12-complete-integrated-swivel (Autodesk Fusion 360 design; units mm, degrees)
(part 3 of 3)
extrude "Extrude2" cut sketch "E Rear Bearing Cap Bolt seed" profile of C1 along normal blind 3 (= "capThickness")
circular_pattern "C-Pattern1" TotalAngle 360
chamfer "Chamfer1" distance 0.3 (= "bedRelief")
work_plane "WorkPlane1" AlongDistance -29 (= "hubFace - adapterThickness") ExtraOffset 0
sketch "F Adapter Flange sketch" plane through (-20.5061, -20.5061, 0) normal (0.7071, 0.7071, 0) x axis (0, 0, 1)
  circle C1 centre (0, 0) radius 38
  dimension "d967" diameter C1 = 76 (= "mountOD")
extrude "Extrude1" new body sketch "F Adapter Flange sketch" along normal blind 6 (= "adapterThickness")
work_plane "WorkPlane2" AlongDistance -23 (= "hubFace") ExtraOffset 0
sketch "F Centering Pilot sketch" plane through (-16.2635, -16.2635, 0) normal (0.7071, 0.7071, 0) x axis (0, 0, 1)
  circle C1 centre (0, 0) radius 25
  circle C2 centre (0, 0) radius 17
  dimension "d972" diameter C1 = 50 (= "pilotDiameter")
  dimension "d973" diameter C2 = 34 (= "pilotInside")
extrude "Extrude2" add sketch "F Centering Pilot sketch" along normal blind 2 (= "pilotHeight")
work_plane "WorkPlane3" AlongDistance -29 (= "hubFace - adapterThickness") ExtraOffset 0
sketch "F Shaft Clearance sketch" plane through (-20.5061, -20.5061, 0) normal (0.7071, 0.7071, 0) x axis (0, 0, 1)
  circle C1 centre (0, 0) radius 4.25
  dimension "d978" diameter C1 = 8.5 (= "shaftClearance")
extrude "Extrude3" cut sketch "F Shaft Clearance sketch" along normal blind 6 (= "adapterThickness")
work_plane "WorkPlane4" AlongDistance -29 (= "hubFace - adapterThickness") ExtraOffset 0
sketch "F Mount Holes" plane through (-20.5061, -20.5061, 0) normal (0.7071, 0.7071, 0) x axis (0, 0, 1)
  circle C1 centre (22.6274, 22.6274) radius 2.15
  circle C2 centre (-22.6274, 22.6274) radius 2.15
  circle C3 centre (-22.6274, -22.6274) radius 2.15
  circle C4 centre (22.6274, -22.6274) radius 2.15
  point P1 (0, 0)
  point P2 (22.6274, 22.6274)
  point P3 (-22.6274, 22.6274)
  point P4 (-22.6274, -22.6274)
  point P5 (22.6274, -22.6274)
  dimension "d983" distance P1 P2 = 22.6274 (= "abs(mountCircle / ( 2 * sqrt(2) ))")
  dimension "d984" distance P1 P2 = 22.6274 (= "abs(mountCircle / ( 2 * sqrt(2) ))")
  dimension "d985" diameter C1 = 4.3 (= "m4Clearance")
  dimension "d986" distance P1 P3 = 22.6274 (= "abs(-mountCircle / ( 2 * sqrt(2) ))")
  dimension "d987" distance P1 P3 = 22.6274 (= "abs(mountCircle / ( 2 * sqrt(2) ))")
  dimension "d988" diameter C2 = 4.3 (= "m4Clearance")
  dimension "d989" distance P1 P4 = 22.6274 (= "abs(-mountCircle / ( 2 * sqrt(2) ))")
  dimension "d990" distance P1 P4 = 22.6274 (= "abs(-mountCircle / ( 2 * sqrt(2) ))")
  dimension "d991" diameter C3 = 4.3 (= "m4Clearance")
  dimension "d992" distance P1 P5 = 22.6274 (= "abs(mountCircle / ( 2 * sqrt(2) ))")
  dimension "d993" distance P1 P5 = 22.6274 (= "abs(-mountCircle / ( 2 * sqrt(2) ))")
  dimension "d994" diameter C4 = 4.3 (= "m4Clearance")
extrude "Extrude4" cut sketch "F Mount Holes" along normal blind 6 (= "adapterThickness")
sketch "F Compression Sleeve Holes" plane through (-20.5061, -20.5061, 0) normal (0.7071, 0.7071, 0) x axis (0, 0, 1)
  line L1 (11.3137, 0) -> (0, 0)
  line L2 (0, 11.3137) -> (0, 0)
  line L3 (-11.3137, 0) -> (0, 0)
  line L4 (0, -11.3137) -> (0, 0)
  circle C1 centre (11.3137, 0) radius 4.1
  circle C2 centre (0, 11.3137) radius 4.1
  circle C3 centre (-11.3137, 0) radius 4.1
  circle C4 centre (0, -11.3137) radius 4.1
  point P1 (0, 0)
  point P2 (11.3137, 0)
  point P3 (0, 11.3137)
  point P5 (0, -11.3137)
  horizontal L1
  vertical L2
  horizontal L3
  vertical L4
  dimension "d997" distance P1 P2 = 11.3137 (= "abs(hubHoleSpacing / sqrt(2))")
  dimension "d998" diameter C1 = 8.2 (= "sleeveOD + sleeveAllowance")
  dimension "d999" distance P1 P3 = 11.3137 (= "abs(hubHoleSpacing / sqrt(2))")
  dimension "d1000" diameter C2 = 8.2 (= "sleeveOD + sleeveAllowance")
  dimension "d59" = 150 (= "bodyWidth")
  dimension "d1002" diameter C3 = 8.2 (= "sleeveOD + sleeveAllowance")
  dimension "d1003" distance P1 P5 = 11.3137 (= "abs(-hubHoleSpacing / sqrt(2))")
  dimension "d1004" diameter C4 = 8.2 (= "sleeveOD + sleeveAllowance")
  dimension "d1001" distance = 11.3137 (= "abs(-hubHoleSpacing / sqrt(2))")
extrude "Extrude5" cut sketch "F Compression Sleeve Holes" profile of C1 C2 C3 C4 along normal blind 6 (= "adapterThickness")
chamfer "Chamfer1" distance 0.4 (= "entryChamfer")
chamfer "Chamfer2" distance 0.3 (= "bedRelief")
work_plane "WorkPlane1" AlongDistance 0.5 (= "qFront") ExtraOffset 0
sketch "Front 608 sketch" plane through (0.3536, 0.3536, 0) normal (0.7071, 0.7071, 0) x axis (0, 0, 1)
  circle C1 centre (0, 0) radius 11
  circle C2 centre (0, 0) radius 4
  dimension "d1011" diameter C1 = 22 (= "bearingOD")
  dimension "d1012" diameter C2 = 8 (= "bearingID")
extrude "Extrude1" new body sketch "Front 608 sketch" along normal blind 7 (= "bearingWidth")
work_plane "WorkPlane2" AlongDistance 25.6 (= "qRearBearing") ExtraOffset 0
sketch "Rear 608 sketch" plane through (18.1019, 18.1019, 0) normal (0.7071, 0.7071, 0) x axis (0, 0, 1)
  circle C1 centre (0, 0) radius 11
  circle C2 centre (0, 0) radius 4
  dimension "d1017" diameter C1 = 22 (= "bearingOD")
  dimension "d1018" diameter C2 = 8 (= "bearingID")
extrude "Extrude2" new body sketch "Rear 608 sketch" along normal blind 7 (= "bearingWidth")
work_plane "WorkPlane1" AlongDistance -24 ExtraOffset 0
sketch "Metal Shaft sketch" plane through (-16.9706, -16.9706, 0) normal (0.7071, 0.7071, 0) x axis (0, 0, 1)
  circle C1 centre (0, 0) radius 4
  dimension "d1023" diameter C1 = 8
extrude "Extrude1" new body sketch "Metal Shaft sketch" along normal blind 60
work_plane "WorkPlane1" AlongDistance -3.5 (= "qFront - 4 mm") ExtraOffset 0
sketch "Front Inner Ring Spacer sketch" plane through (-2.4749, -2.4749, 0) normal (0.7071, 0.7071, 0) x axis (0, 0, 1)
  circle C1 centre (0, 0) radius 5
  circle C2 centre (0, 0) radius 4
  dimension "d1028" diameter C1 = 10
  dimension "d1029" diameter C2 = 8
extrude "Extrude1" new body sketch "Front Inner Ring Spacer sketch" along normal blind 4
work_plane "WorkPlane2" AlongDistance 7.5 (= "qFront + bearingWidth") ExtraOffset 0
sketch "Rear Inner Ring Spacer sketch" plane through (5.3033, 5.3033, 0) normal (0.7071, 0.7071, 0) x axis (0, 0, 1)
  circle C1 centre (0, 0) radius 5
  circle C2 centre (0, 0) radius 4
  dimension "d1034" diameter C1 = 10
  dimension "d1035" diameter C2 = 8
extrude "Extrude2" new body sketch "Rear Inner Ring Spacer sketch" along normal blind 4
work_plane "WorkPlane1" AlongDistance -12.5 (= "qFront - 13 mm") ExtraOffset 0
sketch "Front Collar Maximum Envelope sketch" plane through (-8.8388, -8.8388, 0) normal (0.7071, 0.7071, 0) x axis (0, 0, 1)
  circle C1 centre (0, 0) radius 11.2
  circle C2 centre (0, 0) radius 4
  dimension "d1040" diameter C1 = 22.4
  dimension "d1041" diameter C2 = 8
extrude "Extrude1" new body sketch "Front Collar Maximum Envelope sketch" along normal blind 9
work_plane "WorkPlane2" AlongDistance 11.5 (= "qFront + bearingWidth + 4 mm") ExtraOffset 0
sketch "Rear Collar Maximum Envelope sketch" plane through (8.1317, 8.1317, 0) normal (0.7071, 0.7071, 0) x axis (0, 0, 1)
  circle C1 centre (0, 0) radius 11.2
  circle C2 centre (0, 0) radius 4
  dimension "d1046" diameter C1 = 22.4
  dimension "d1047" diameter C2 = 8
extrude "Extrude2" new body sketch "Rear Collar Maximum Envelope sketch" along normal blind 9
work_plane "WorkPlane1" AlongDistance 0 ExtraOffset 0
sketch "Spacer Pattern Axis" plane through (0, 0, 0) normal (0.7071, 0.7071, 0) x axis (0, 0, 1)
  circle C1 centre (0, 0) radius 0.5
  dimension "d1052" diameter C1 = 1
work_plane "WorkPlane2" AlongDistance 10.6 (= "qFrontBack") ExtraOffset 0
sketch "Support Spacer OD" plane through (7.4953, 7.4953, 0) normal (0.7071, 0.7071, 0) x axis (0, 0, 1)
  line L1 (17, 0) -> (0, 0)
  circle C1 centre (17, 0) radius 3
  circle C2 centre (17, 0) radius 1.6
  point P1 (0, 0)
  point P2 (17, 0)
  horizontal L1
  dimension "d1055" distance P1 P2 = 17 (= "supportCircle / 2")
  dimension "d1056" diameter C1 = 6 (= "supportSpacerOD")
  dimension "d1057" diameter C2 = 3.2
extrude "Extrude1" new body sketch "Support Spacer OD" profile of C1 C2 along normal blind 12 (= "supportSpacer")
circular_pattern "C-Pattern1" TotalAngle 360
work_plane "WorkPlane1" AlongDistance -29 (= "hubFace - adapterThickness") ExtraOffset 0
sketch "Sleeve 1 Outer" plane through (-20.5061, -20.5061, 0) normal (0.7071, 0.7071, 0) x axis (0, 0, 1)
  line L1 (11.3137, 0) -> (0, 0)
  circle C1 centre (11.3137, 0) radius 4
  circle C2 centre (11.3137, 0) radius 2.15
  point P1 (0, 0)
  point P2 (11.3137, 0)
  horizontal L1
  dimension "d1064" distance P1 P2 = 11.3137 (= "abs(hubHoleSpacing / sqrt(2))")
  dimension "d1065" diameter C1 = 8 (= "sleeveOD")
  dimension "d1066" diameter C2 = 4.3
extrude "Extrude1" new body sketch "Sleeve 1 Outer" profile of C1 C2 along normal blind 6 (= "adapterThickness")
work_plane "WorkPlane2" AlongDistance -29 (= "hubFace - adapterThickness") ExtraOffset 0
sketch "Sleeve 2 Outer" plane through (-20.5061, -20.5061, 0) normal (0.7071, 0.7071, 0) x axis (0, 0, 1)
  line L1 (0, 11.3137) -> (0, 0)
  circle C1 centre (0, 11.3137) radius 4
  circle C2 centre (0, 11.3137) radius 2.15
  point P1 (0, 0)
  point P2 (0, 11.3137)
  vertical L1
  dimension "d1071" distance P1 P2 = 11.3137 (= "abs(hubHoleSpacing / sqrt(2))")
  dimension "d1072" diameter C1 = 8 (= "sleeveOD")
  dimension "d1073" diameter C2 = 4.3
extrude "Extrude2" new body sketch "Sleeve 2 Outer" profile of C1 C2 along normal blind 6 (= "adapterThickness")
work_plane "WorkPlane3" AlongDistance -29 (= "hubFace - adapterThickness") ExtraOffset 0
sketch "Sleeve 3 Outer" plane through (-20.5061, -20.5061, 0) normal (0.7071, 0.7071, 0) x axis (0, 0, 1)
  line L1 (-11.3137, 0) -> (0, 0)
  circle C1 centre (-11.3137, 0) radius 4
  circle C2 centre (-11.3137, 0) radius 2.15
  point P1 (0, 0)
  point P2 (-11.3137, 0)
  horizontal L1
  dimension "d1078" distance P1 P2 = 11.3137 (= "abs(-hubHoleSpacing / sqrt(2))")
  dimension "d1079" diameter C1 = 8 (= "sleeveOD")
  dimension "d1080" diameter C2 = 4.3
extrude "Extrude3" new body sketch "Sleeve 3 Outer" profile of C1 C2 along normal blind 6 (= "adapterThickness")
work_plane "WorkPlane4" AlongDistance -29 (= "hubFace - adapterThickness") ExtraOffset 0
sketch "Sleeve 4 Outer" plane through (-20.5061, -20.5061, 0) normal (0.7071, 0.7071, 0) x axis (0, 0, 1)
  line L1 (0, -11.3137) -> (0, 0)
  circle C1 centre (0, -11.3137) radius 4
  circle C2 centre (0, -11.3137) radius 2.15
  point P1 (0, 0)
  point P2 (0, -11.3137)
  vertical L1
  dimension "d1085" distance P1 P2 = 11.3137 (= "abs(-hubHoleSpacing / sqrt(2))")
  dimension "d1086" diameter C1 = 8 (= "sleeveOD")
  dimension "d1087" diameter C2 = 4.3
extrude "Extrude4" new body sketch "Sleeve 4 Outer" profile of C1 C2 along normal blind 6 (= "adapterThickness")
work_plane "WorkPlane1" AlongDistance -23 (= "hubFace") ExtraOffset 0
sketch "Sonic Hub Body sketch" plane through (-16.2635, -16.2635, 0) normal (0.7071, 0.7071, 0) x axis (0, 0, 1)
  circle C1 centre (0, 0) radius 16
  circle C2 centre (0, 0) radius 4
  dimension "d1092" diameter C1 = 32
  dimension "d1093" diameter C2 = 8
extrude "Extrude1" new body sketch "Sonic Hub Body sketch" along normal blind 8
work_plane "WorkPlane2" AlongDistance -15 (= "hubFace + 8 mm") ExtraOffset 0
sketch "Sonic Hub Pilot sketch" plane through (-10.6066, -10.6066, 0) normal (0.7071, 0.7071, 0) x axis (0, 0, 1)
  circle C1 centre (0, 0) radius 7
  circle C2 centre (0, 0) radius 4
  dimension "d1098" diameter C1 = 14
  dimension "d1099" diameter C2 = 8
extrude "Extrude2" add sketch "Sonic Hub Pilot sketch" along normal blind 2
work_plane "WorkPlane3" AlongDistance -23 (= "hubFace") ExtraOffset 0
sketch "Hub M4 Thread Envelopes" plane through (-16.2635, -16.2635, 0) normal (0.7071, 0.7071, 0) x axis (0, 0, 1)
  line L1 (11.3137, 0) -> (0, 0)
  line L2 (0, 11.3137) -> (0, 0)
  line L3 (-11.3137, 0) -> (0, 0)
  line L4 (0, -11.3137) -> (0, 0)
  circle C1 centre (11.3137, 0) radius 2.15
  circle C2 centre (0, 11.3137) radius 2.15
  circle C3 centre (-11.3137, 0) radius 2.15
  circle C4 centre (0, -11.3137) radius 2.15
  point P1 (0, 0)
  point P2 (11.3137, 0)
  point P3 (0, 11.3137)
  point P5 (0, -11.3137)
  horizontal L1
  vertical L2
  horizontal L3
  vertical L4
  dimension "d1104" distance P1 P2 = 11.3137 (= "abs(hubHoleSpacing / sqrt(2))")
  dimension "d1105" diameter C1 = 4.3
  dimension "d1106" distance P1 P3 = 11.3137 (= "abs(hubHoleSpacing / sqrt(2))")
  dimension "d1107" diameter C2 = 4.3
  dimension "d59" = 150 (= "bodyWidth")
  dimension "d1109" diameter C3 = 4.3
  dimension "d1110" distance P1 P5 = 11.3137 (= "abs(-hubHoleSpacing / sqrt(2))")
  dimension "d1111" diameter C4 = 4.3
  dimension "d1108" distance = 11.3137 (= "abs(-hubHoleSpacing / sqrt(2))")
extrude "Extrude3" cut sketch "Hub M4 Thread Envelopes" profile of C1 C2 C3 C4 along normal blind 8
work_plane "WorkPlane1" AlongDistance -30 (= "hubFace - adapterThickness - 1 mm") ExtraOffset 0
sketch "Hub Screw 1 Profile" plane through (-21.2132, -21.2132, 0) normal (0.7071, 0.7071, 0) x axis (0, 0, 1)
  line L1 (11.3137, 0) -> (0, 0)
  circle C1 centre (11.3137, 0) radius 2
  point P1 (0, 0)
  point P2 (11.3137, 0)
  horizontal L1
  dimension "d1116" distance P1 P2 = 11.3137 (= "abs(hubHoleSpacing / sqrt(2))")
  dimension "d1117" diameter C1 = 4
extrude "Extrude1" new body sketch "Hub Screw 1 Profile" profile of C1 along normal blind 12
work_plane "WorkPlane2" AlongDistance -34 (= "hubFace - adapterThickness - 5 mm") ExtraOffset 0
sketch "Hub Screw Head 1 Profile" plane through (-24.0416, -24.0416, 0) normal (0.7071, 0.7071, 0) x axis (0, 0, 1)
  line L1 (11.3137, 0) -> (0, 0)
  circle C1 centre (11.3137, 0) radius 3.5
  point P1 (0, 0)
  point P2 (11.3137, 0)
  horizontal L1
  dimension "d1122" distance P1 P2 = 11.3137 (= "abs(hubHoleSpacing / sqrt(2))")
  dimension "d1123" diameter C1 = 7
extrude "Extrude2" new body sketch "Hub Screw Head 1 Profile" profile of C1 along normal blind 4
work_plane "WorkPlane3" AlongDistance -30 (= "hubFace - adapterThickness - 1 mm") ExtraOffset 0
sketch "Hub Washer 1 Outer" plane through (-21.2132, -21.2132, 0) normal (0.7071, 0.7071, 0) x axis (0, 0, 1)
  line L1 (11.3137, 0) -> (0, 0)
  circle C1 centre (11.3137, 0) radius 6
  circle C2 centre (11.3137, 0) radius 2.15
  point P1 (0, 0)
  point P2 (11.3137, 0)
  horizontal L1
  dimension "d1128" distance P1 P2 = 11.3137 (= "abs(hubHoleSpacing / sqrt(2))")
  dimension "d1129" diameter C1 = 12
  dimension "d1130" diameter C2 = 4.3
extrude "Extrude3" new body sketch "Hub Washer 1 Outer" profile of C1 C2 along normal blind 1
work_plane "WorkPlane4" AlongDistance -30 (= "hubFace - adapterThickness - 1 mm") ExtraOffset 0
sketch "Hub Screw 2 Profile" plane through (-21.2132, -21.2132, 0) normal (0.7071, 0.7071, 0) x axis (0, 0, 1)
  line L1 (0, 11.3137) -> (0, 0)
  circle C1 centre (0, 11.3137) radius 2
  point P1 (0, 0)
  point P2 (0, 11.3137)
  vertical L1
  dimension "d1135" distance P1 P2 = 11.3137 (= "abs(hubHoleSpacing / sqrt(2))")
  dimension "d1136" diameter C1 = 4
extrude "Extrude4" new body sketch "Hub Screw 2 Profile" profile of C1 along normal blind 12
work_plane "WorkPlane5" AlongDistance -34 (= "hubFace - adapterThickness - 5 mm") ExtraOffset 0
sketch "Hub Screw Head 2 Profile" plane through (-24.0416, -24.0416, 0) normal (0.7071, 0.7071, 0) x axis (0, 0, 1)
  line L1 (0, 11.3137) -> (0, 0)
  circle C1 centre (0, 11.3137) radius 3.5
  point P1 (0, 0)
  point P2 (0, 11.3137)
  vertical L1
  dimension "d1141" distance P1 P2 = 11.3137 (= "abs(hubHoleSpacing / sqrt(2))")
  dimension "d1142" diameter C1 = 7
extrude "Extrude5" new body sketch "Hub Screw Head 2 Profile" profile of C1 along normal blind 4
work_plane "WorkPlane6" AlongDistance -30 (= "hubFace - adapterThickness - 1 mm") ExtraOffset 0
sketch "Hub Washer 2 Outer" plane through (-21.2132, -21.2132, 0) normal (0.7071, 0.7071, 0) x axis (0, 0, 1)
  line L1 (0, 11.3137) -> (0, 0)
  circle C1 centre (0, 11.3137) radius 6
  circle C2 centre (0, 11.3137) radius 2.15
  point P1 (0, 0)
  point P2 (0, 11.3137)
  vertical L1
  dimension "d1147" distance P1 P2 = 11.3137 (= "abs(hubHoleSpacing / sqrt(2))")
  dimension "d1148" diameter C1 = 12
  dimension "d1149" diameter C2 = 4.3
extrude "Extrude6" new body sketch "Hub Washer 2 Outer" profile of C1 C2 along normal blind 1
work_plane "WorkPlane7" AlongDistance -30 (= "hubFace - adapterThickness - 1 mm") ExtraOffset 0
sketch "Hub Screw 3 Profile" plane through (-21.2132, -21.2132, 0) normal (0.7071, 0.7071, 0) x axis (0, 0, 1)
  line L1 (-11.3137, 0) -> (0, 0)
  circle C1 centre (-11.3137, 0) radius 2
  point P1 (0, 0)
  point P2 (-11.3137, 0)
  horizontal L1
  dimension "d1154" distance P1 P2 = 11.3137 (= "abs(-hubHoleSpacing / sqrt(2))")
  dimension "d1155" diameter C1 = 4
extrude "Extrude7" new body sketch "Hub Screw 3 Profile" profile of C1 along normal blind 12
work_plane "WorkPlane8" AlongDistance -34 (= "hubFace - adapterThickness - 5 mm") ExtraOffset 0
sketch "Hub Screw Head 3 Profile" plane through (-24.0416, -24.0416, 0) normal (0.7071, 0.7071, 0) x axis (0, 0, 1)
  line L1 (-11.3137, 0) -> (0, 0)
  circle C1 centre (-11.3137, 0) radius 3.5
  point P1 (0, 0)
  point P2 (-11.3137, 0)
  horizontal L1
  dimension "d1160" distance P1 P2 = 11.3137 (= "abs(-hubHoleSpacing / sqrt(2))")
  dimension "d1161" diameter C1 = 7
extrude "Extrude8" new body sketch "Hub Screw Head 3 Profile" profile of C1 along normal blind 4
work_plane "WorkPlane9" AlongDistance -30 (= "hubFace - adapterThickness - 1 mm") ExtraOffset 0
sketch "Hub Washer 3 Outer" plane through (-21.2132, -21.2132, 0) normal (0.7071, 0.7071, 0) x axis (0, 0, 1)
  line L1 (-11.3137, 0) -> (0, 0)
  circle C1 centre (-11.3137, 0) radius 6
  circle C2 centre (-11.3137, 0) radius 2.15
  point P1 (0, 0)
  point P2 (-11.3137, 0)
  horizontal L1
  dimension "d1166" distance P1 P2 = 11.3137 (= "abs(-hubHoleSpacing / sqrt(2))")
  dimension "d1167" diameter C1 = 12
  dimension "d1168" diameter C2 = 4.3
extrude "Extrude9" new body sketch "Hub Washer 3 Outer" profile of C1 C2 along normal blind 1
work_plane "WorkPlane10" AlongDistance -30 (= "hubFace - adapterThickness - 1 mm") ExtraOffset 0
sketch "Hub Screw 4 Profile" plane through (-21.2132, -21.2132, 0) normal (0.7071, 0.7071, 0) x axis (0, 0, 1)
  line L1 (0, -11.3137) -> (0, 0)
  circle C1 centre (0, -11.3137) radius 2
  point P1 (0, 0)
  point P2 (0, -11.3137)
  vertical L1
  dimension "d1173" distance P1 P2 = 11.3137 (= "abs(-hubHoleSpacing / sqrt(2))")
  dimension "d1174" diameter C1 = 4
extrude "Extrude10" new body sketch "Hub Screw 4 Profile" profile of C1 along normal blind 12
work_plane "WorkPlane11" AlongDistance -34 (= "hubFace - adapterThickness - 5 mm") ExtraOffset 0
sketch "Hub Screw Head 4 Profile" plane through (-24.0416, -24.0416, 0) normal (0.7071, 0.7071, 0) x axis (0, 0, 1)
  line L1 (0, -11.3137) -> (0, 0)
  circle C1 centre (0, -11.3137) radius 3.5
  point P1 (0, 0)
  point P2 (0, -11.3137)
  vertical L1
  dimension "d1179" distance P1 P2 = 11.3137 (= "abs(-hubHoleSpacing / sqrt(2))")
  dimension "d1180" diameter C1 = 7
extrude "Extrude11" new body sketch "Hub Screw Head 4 Profile" profile of C1 along normal blind 4
work_plane "WorkPlane12" AlongDistance -30 (= "hubFace - adapterThickness - 1 mm") ExtraOffset 0
sketch "Hub Washer 4 Outer" plane through (-21.2132, -21.2132, 0) normal (0.7071, 0.7071, 0) x axis (0, 0, 1)
  line L1 (0, -11.3137) -> (0, 0)
  circle C1 centre (0, -11.3137) radius 6
  circle C2 centre (0, -11.3137) radius 2.15
  point P1 (0, 0)
  point P2 (0, -11.3137)
  vertical L1
  dimension "d1185" distance P1 P2 = 11.3137 (= "abs(-hubHoleSpacing / sqrt(2))")
  dimension "d1186" diameter C1 = 12
  dimension "d1187" diameter C2 = 4.3
extrude "Extrude12" new body sketch "Hub Washer 4 Outer" profile of C1 C2 along normal blind 1
work_plane "WorkPlane1" AlongDistance -30 (= "hubFace - adapterThickness - 1 mm") ExtraOffset 0
sketch "Adapter Screw 1 Profile" plane through (-21.2132, -21.2132, 0) normal (0.7071, 0.7071, 0) x axis (0, 0, 1)
  circle C1 centre (22.6274, 22.6274) radius 2
  point P1 (0, 0)
  point P2 (22.6274, 22.6274)
  dimension "d1192" distance P1 P2 = 22.6274 (= "abs(mountCircle / ( 2 * sqrt(2) ))")
  dimension "d1193" distance P1 P2 = 22.6274 (= "abs(mountCircle / ( 2 * sqrt(2) ))")
  dimension "d1194" diameter C1 = 4
extrude "Extrude1" new body sketch "Adapter Screw 1 Profile" along normal blind 30
work_plane "WorkPlane2" AlongDistance -34 (= "hubFace - adapterThickness - 5 mm") ExtraOffset 0
sketch "Adapter Screw Head 1 Profile" plane through (-24.0416, -24.0416, 0) normal (0.7071, 0.7071, 0) x axis (0, 0, 1)
  circle C1 centre (22.6274, 22.6274) radius 3.5
  point P1 (0, 0)
  point P2 (22.6274, 22.6274)
  dimension "d1199" distance P1 P2 = 22.6274 (= "abs(mountCircle / ( 2 * sqrt(2) ))")
  dimension "d1200" distance P1 P2 = 22.6274 (= "abs(mountCircle / ( 2 * sqrt(2) ))")
  dimension "d1201" diameter C1 = 7
extrude "Extrude2" new body sketch "Adapter Screw Head 1 Profile" along normal blind 4
work_plane "WorkPlane3" AlongDistance -30 (= "hubFace - adapterThickness - 1 mm") ExtraOffset 0
sketch "Adapter Washer 1 Outer" plane through (-21.2132, -21.2132, 0) normal (0.7071, 0.7071, 0) x axis (0, 0, 1)
  circle C1 centre (22.6274, 22.6274) radius 4.5
  circle C2 centre (22.6274, 22.6274) radius 2.15
  point P1 (0, 0)
  point P2 (22.6274, 22.6274)
  dimension "d1206" distance P1 P2 = 22.6274 (= "abs(mountCircle / ( 2 * sqrt(2) ))")
  dimension "d1207" distance P1 P2 = 22.6274 (= "abs(mountCircle / ( 2 * sqrt(2) ))")
  dimension "d1208" diameter C1 = 9
  dimension "d1209" diameter C2 = 4.3
extrude "Extrude3" new body sketch "Adapter Washer 1 Outer" along normal blind 1
work_plane "WorkPlane4" ExtraOffset 0
sketch "Adapter Nut Hex 1" plane through (-3.182, -3.182, 0) normal (0.7071, 0.7071, 0) x axis (0, 0, 1)
  line L1 (24.6481, 26.1274) -> (26.6689, 22.6274)
  line L2 (20.6067, 26.1274) -> (24.6481, 26.1274)
  line L3 (18.586, 22.6274) -> (20.6067, 26.1274)
  line L4 (20.6067, 19.1274) -> (18.586, 22.6274)
  line L5 (24.6481, 19.1274) -> (20.6067, 19.1274)
  line L6 (26.6689, 22.6274) -> (24.6481, 19.1274)
  circle C1 centre (22.6274, 22.6274) radius 4.0415
  point P3 (26.6689, 22.6274)
  point P4 (24.6481, 26.1274)
  point P5 (20.6067, 26.1274)
  point P6 (18.586, 22.6274)
  point P7 (20.6067, 19.1274)
  point P8 (24.6481, 19.1274)
  point P1 (0, 0)
  point P2 (22.6274, 22.6274)
  coincident C1 P3
  coincident C1 P4
  coincident C1 P5
  coincident C1 P6
  coincident C1 P7
  coincident C1 P8
  equal L1 L2
  equal L1 L3
  equal L1 L4
  equal L1 L5
  equal L1 L6
  horizontal L2
  dimension "d1214" distance P1 P2 = 22.6274 (= "abs(mountCircle / ( 2 * sqrt(2) ))")
  dimension "d1215" distance P1 P2 = 22.6274 (= "abs(mountCircle / ( 2 * sqrt(2) ))")
  dimension "d1216" diameter C1 = 8.0829 (= "2 * ( 7 mm ) / sqrt(3)")
extrude "Extrude4" new body sketch "Adapter Nut Hex 1" profile of L1 L2 L3 L4 L5 L6 along normal blind 3.2
sketch "Nut Thread Clearance 1" plane through (-3.182, -3.182, 0) normal (0.7071, 0.7071, 0) x axis (0, 0, 1)
  circle C1 centre (22.6274, 22.6274) radius 2.15
  point P1 (0, 0)
  point P2 (22.6274, 22.6274)
  dimension "d1219" distance P1 P2 = 22.6274 (= "abs(mountCircle / ( 2 * sqrt(2) ))")
  dimension "d1220" distance P1 P2 = 22.6274 (= "abs(mountCircle / ( 2 * sqrt(2) ))")
  dimension "d1221" diameter C1 = 4.3
extrude "Extrude5" cut sketch "Nut Thread Clearance 1" along normal blind 3.2
work_plane "WorkPlane5" AlongDistance -30 (= "hubFace - adapterThickness - 1 mm") ExtraOffset 0
sketch "Adapter Screw 2 Profile" plane through (-21.2132, -21.2132, 0) normal (0.7071, 0.7071, 0) x axis (0, 0, 1)
  circle C1 centre (-22.6274, 22.6274) radius 2
  point P1 (0, 0)
  point P2 (-22.6274, 22.6274)
  dimension "d1226" distance P1 P2 = 22.6274 (= "abs(-mountCircle / ( 2 * sqrt(2) ))")
  dimension "d1227" distance P1 P2 = 22.6274 (= "abs(mountCircle / ( 2 * sqrt(2) ))")
  dimension "d1228" diameter C1 = 4
extrude "Extrude6" new body sketch "Adapter Screw 2 Profile" along normal blind 30
work_plane "WorkPlane6" AlongDistance -34 (= "hubFace - adapterThickness - 5 mm") ExtraOffset 0
sketch "Adapter Screw Head 2 Profile" plane through (-24.0416, -24.0416, 0) normal (0.7071, 0.7071, 0) x axis (0, 0, 1)
  circle C1 centre (-22.6274, 22.6274) radius 3.5
  point P1 (0, 0)
  point P2 (-22.6274, 22.6274)
  dimension "d1233" distance P1 P2 = 22.6274 (= "abs(-mountCircle / ( 2 * sqrt(2) ))")
  dimension "d1234" distance P1 P2 = 22.6274 (= "abs(mountCircle / ( 2 * sqrt(2) ))")
  dimension "d1235" diameter C1 = 7
extrude "Extrude7" new body sketch "Adapter Screw Head 2 Profile" along normal blind 4
work_plane "WorkPlane7" AlongDistance -30 (= "hubFace - adapterThickness - 1 mm") ExtraOffset 0
sketch "Adapter Washer 2 Outer" plane through (-21.2132, -21.2132, 0) normal (0.7071, 0.7071, 0) x axis (0, 0, 1)
  circle C1 centre (-22.6274, 22.6274) radius 4.5
  circle C2 centre (-22.6274, 22.6274) radius 2.15
  point P1 (0, 0)
  point P2 (-22.6274, 22.6274)
  dimension "d1240" distance P1 P2 = 22.6274 (= "abs(-mountCircle / ( 2 * sqrt(2) ))")
  dimension "d1241" distance P1 P2 = 22.6274 (= "abs(mountCircle / ( 2 * sqrt(2) ))")
  dimension "d1242" diameter C1 = 9
  dimension "d1243" diameter C2 = 4.3
extrude "Extrude8" new body sketch "Adapter Washer 2 Outer" along normal blind 1
work_plane "WorkPlane8" ExtraOffset 0
sketch "Adapter Nut Hex 2" plane through (-3.182, -3.182, 0) normal (0.7071, 0.7071, 0) x axis (0, 0, 1)
  line L1 (-20.6067, 26.1274) -> (-18.586, 22.6274)
  line L2 (-24.6481, 26.1274) -> (-20.6067, 26.1274)
  line L3 (-26.6689, 22.6274) -> (-24.6481, 26.1274)
  line L4 (-24.6481, 19.1274) -> (-26.6689, 22.6274)
  line L5 (-20.6067, 19.1274) -> (-24.6481, 19.1274)
  line L6 (-18.586, 22.6274) -> (-20.6067, 19.1274)
  circle C1 centre (-22.6274, 22.6274) radius 4.0415
  point P3 (-18.586, 22.6274)
  point P4 (-20.6067, 26.1274)
  point P5 (-24.6481, 26.1274)
  point P6 (-26.6689, 22.6274)
  point P7 (-24.6481, 19.1274)
  point P8 (-20.6067, 19.1274)
  point P1 (0, 0)
  point P2 (-22.6274, 22.6274)
  coincident C1 P3
  coincident C1 P4
  coincident C1 P5
  coincident C1 P6
  coincident C1 P7
  coincident C1 P8
  equal L1 L2
  equal L1 L3
  equal L1 L4
  equal L1 L5
  equal L1 L6
  horizontal L2
  dimension "d1248" distance P1 P2 = 22.6274 (= "abs(-mountCircle / ( 2 * sqrt(2) ))")
  dimension "d1249" distance P1 P2 = 22.6274 (= "abs(mountCircle / ( 2 * sqrt(2) ))")
  dimension "d1250" diameter C1 = 8.0829 (= "2 * ( 7 mm ) / sqrt(3)")
extrude "Extrude9" new body sketch "Adapter Nut Hex 2" profile of L1 L2 L3 L4 L5 L6 along normal blind 3.2
sketch "Nut Thread Clearance 2" plane through (-3.182, -3.182, 0) normal (0.7071, 0.7071, 0) x axis (0, 0, 1)
  circle C1 centre (-22.6274, 22.6274) radius 2.15
  point P1 (0, 0)
  point P2 (-22.6274, 22.6274)
  dimension "d1253" distance P1 P2 = 22.6274 (= "abs(-mountCircle / ( 2 * sqrt(2) ))")
  dimension "d1254" distance P1 P2 = 22.6274 (= "abs(mountCircle / ( 2 * sqrt(2) ))")
  dimension "d1255" diameter C1 = 4.3
extrude "Extrude10" cut sketch "Nut Thread Clearance 2" along normal blind 3.2
work_plane "WorkPlane9" AlongDistance -30 (= "hubFace - adapterThickness - 1 mm") ExtraOffset 0
sketch "Adapter Screw 3 Profile" plane through (-21.2132, -21.2132, 0) normal (0.7071, 0.7071, 0) x axis (0, 0, 1)
  circle C1 centre (-22.6274, -22.6274) radius 2
  point P1 (0, 0)
  point P2 (-22.6274, -22.6274)
  dimension "d1260" distance P1 P2 = 22.6274 (= "abs(-mountCircle / ( 2 * sqrt(2) ))")
  dimension "d1261" distance P1 P2 = 22.6274 (= "abs(-mountCircle / ( 2 * sqrt(2) ))")
  dimension "d1262" diameter C1 = 4
extrude "Extrude11" new body sketch "Adapter Screw 3 Profile" along normal blind 30
work_plane "WorkPlane10" AlongDistance -34 (= "hubFace - adapterThickness - 5 mm") ExtraOffset 0
sketch "Adapter Screw Head 3 Profile" plane through (-24.0416, -24.0416, 0) normal (0.7071, 0.7071, 0) x axis (0, 0, 1)
  circle C1 centre (-22.6274, -22.6274) radius 3.5
  point P1 (0, 0)
  point P2 (-22.6274, -22.6274)
  dimension "d1267" distance P1 P2 = 22.6274 (= "abs(-mountCircle / ( 2 * sqrt(2) ))")
  dimension "d1268" distance P1 P2 = 22.6274 (= "abs(-mountCircle / ( 2 * sqrt(2) ))")
  dimension "d1269" diameter C1 = 7
extrude "Extrude12" new body sketch "Adapter Screw Head 3 Profile" along normal blind 4
work_plane "WorkPlane11" AlongDistance -30 (= "hubFace - adapterThickness - 1 mm") ExtraOffset 0
sketch "Adapter Washer 3 Outer" plane through (-21.2132, -21.2132, 0) normal (0.7071, 0.7071, 0) x axis (0, 0, 1)
  circle C1 centre (-22.6274, -22.6274) radius 4.5
  circle C2 centre (-22.6274, -22.6274) radius 2.15
  point P1 (0, 0)
  point P2 (-22.6274, -22.6274)
  dimension "d1274" distance P1 P2 = 22.6274 (= "abs(-mountCircle / ( 2 * sqrt(2) ))")
  dimension "d1275" distance P1 P2 = 22.6274 (= "abs(-mountCircle / ( 2 * sqrt(2) ))")
  dimension "d1276" diameter C1 = 9
  dimension "d1277" diameter C2 = 4.3
extrude "Extrude13" new body sketch "Adapter Washer 3 Outer" along normal blind 1
work_plane "WorkPlane12" ExtraOffset 0
sketch "Adapter Nut Hex 3" plane through (-3.182, -3.182, 0) normal (0.7071, 0.7071, 0) x axis (0, 0, 1)
  line L1 (-20.6067, -19.1274) -> (-18.586, -22.6274)
  line L2 (-24.6481, -19.1274) -> (-20.6067, -19.1274)
  line L3 (-26.6689, -22.6274) -> (-24.6481, -19.1274)
  line L4 (-24.6481, -26.1274) -> (-26.6689, -22.6274)
  line L5 (-20.6067, -26.1274) -> (-24.6481, -26.1274)
  line L6 (-18.586, -22.6274) -> (-20.6067, -26.1274)
  circle C1 centre (-22.6274, -22.6274) radius 4.0415
  point P3 (-18.586, -22.6274)
  point P4 (-20.6067, -19.1274)
  point P5 (-24.6481, -19.1274)
  point P6 (-26.6689, -22.6274)
  point P7 (-24.6481, -26.1274)
  point P8 (-20.6067, -26.1274)
  point P1 (0, 0)
  point P2 (-22.6274, -22.6274)
  coincident C1 P3
  coincident C1 P4
  coincident C1 P5
  coincident C1 P6
  coincident C1 P7
  coincident C1 P8
  equal L1 L2
  equal L1 L3
  equal L1 L4
  equal L1 L5
  equal L1 L6
  horizontal L2
  dimension "d1282" distance P1 P2 = 22.6274 (= "abs(-mountCircle / ( 2 * sqrt(2) ))")
  dimension "d1283" distance P1 P2 = 22.6274 (= "abs(-mountCircle / ( 2 * sqrt(2) ))")
  dimension "d1284" diameter C1 = 8.0829 (= "2 * ( 7 mm ) / sqrt(3)")
extrude "Extrude14" new body sketch "Adapter Nut Hex 3" profile of L1 L2 L3 L4 L5 L6 along normal blind 3.2
sketch "Nut Thread Clearance 3" plane through (-3.182, -3.182, 0) normal (0.7071, 0.7071, 0) x axis (0, 0, 1)
  circle C1 centre (-22.6274, -22.6274) radius 2.15
  point P1 (0, 0)
  point P2 (-22.6274, -22.6274)
  dimension "d1287" distance P1 P2 = 22.6274 (= "abs(-mountCircle / ( 2 * sqrt(2) ))")
  dimension "d1288" distance P1 P2 = 22.6274 (= "abs(-mountCircle / ( 2 * sqrt(2) ))")
  dimension "d1289" diameter C1 = 4.3
extrude "Extrude15" cut sketch "Nut Thread Clearance 3" along normal blind 3.2
work_plane "WorkPlane13" AlongDistance -30 (= "hubFace - adapterThickness - 1 mm") ExtraOffset 0
sketch "Adapter Screw 4 Profile" plane through (-21.2132, -21.2132, 0) normal (0.7071, 0.7071, 0) x axis (0, 0, 1)
  circle C1 centre (22.6274, -22.6274) radius 2
  point P1 (0, 0)
  point P2 (22.6274, -22.6274)
  dimension "d1294" distance P1 P2 = 22.6274 (= "abs(mountCircle / ( 2 * sqrt(2) ))")
  dimension "d1295" distance P1 P2 = 22.6274 (= "abs(-mountCircle / ( 2 * sqrt(2) ))")
  dimension "d1296" diameter C1 = 4
extrude "Extrude16" new body sketch "Adapter Screw 4 Profile" along normal blind 30
work_plane "WorkPlane14" AlongDistance -34 (= "hubFace - adapterThickness - 5 mm") ExtraOffset 0
sketch "Adapter Screw Head 4 Profile" plane through (-24.0416, -24.0416, 0) normal (0.7071, 0.7071, 0) x axis (0, 0, 1)
  circle C1 centre (22.6274, -22.6274) radius 3.5
  point P1 (0, 0)
  point P2 (22.6274, -22.6274)
  dimension "d1301" distance P1 P2 = 22.6274 (= "abs(mountCircle / ( 2 * sqrt(2) ))")
  dimension "d1302" distance P1 P2 = 22.6274 (= "abs(-mountCircle / ( 2 * sqrt(2) ))")
  dimension "d1303" diameter C1 = 7
extrude "Extrude17" new body sketch "Adapter Screw Head 4 Profile" along normal blind 4
work_plane "WorkPlane15" AlongDistance -30 (= "hubFace - adapterThickness - 1 mm") ExtraOffset 0
sketch "Adapter Washer 4 Outer" plane through (-21.2132, -21.2132, 0) normal (0.7071, 0.7071, 0) x axis (0, 0, 1)
  circle C1 centre (22.6274, -22.6274) radius 4.5
  circle C2 centre (22.6274, -22.6274) radius 2.15
  point P1 (0, 0)
  point P2 (22.6274, -22.6274)
  dimension "d1308" distance P1 P2 = 22.6274 (= "abs(mountCircle / ( 2 * sqrt(2) ))")
  dimension "d1309" distance P1 P2 = 22.6274 (= "abs(-mountCircle / ( 2 * sqrt(2) ))")
  dimension "d1310" diameter C1 = 9
  dimension "d1311" diameter C2 = 4.3
extrude "Extrude18" new body sketch "Adapter Washer 4 Outer" along normal blind 1
work_plane "WorkPlane16" ExtraOffset 0
sketch "Adapter Nut Hex 4" plane through (-3.182, -3.182, 0) normal (0.7071, 0.7071, 0) x axis (0, 0, 1)
  line L1 (24.6481, -19.1274) -> (26.6689, -22.6274)
  line L2 (20.6067, -19.1274) -> (24.6481, -19.1274)
  line L3 (18.586, -22.6274) -> (20.6067, -19.1274)
  line L4 (20.6067, -26.1274) -> (18.586, -22.6274)
  line L5 (24.6481, -26.1274) -> (20.6067, -26.1274)
  line L6 (26.6689, -22.6274) -> (24.6481, -26.1274)
  circle C1 centre (22.6274, -22.6274) radius 4.0415
  point P3 (26.6689, -22.6274)
  point P4 (24.6481, -19.1274)
  point P5 (20.6067, -19.1274)
  point P6 (18.586, -22.6274)
  point P7 (20.6067, -26.1274)
  point P8 (24.6481, -26.1274)
  point P1 (0, 0)
  point P2 (22.6274, -22.6274)
  coincident C1 P3
  coincident C1 P4
  coincident C1 P5
  coincident C1 P6
  coincident C1 P7
  coincident C1 P8
  equal L1 L2
  equal L1 L3
  equal L1 L4
  equal L1 L5
  equal L1 L6
  horizontal L2
  dimension "d1316" distance P1 P2 = 22.6274 (= "abs(mountCircle / ( 2 * sqrt(2) ))")
  dimension "d1317" distance P1 P2 = 22.6274 (= "abs(-mountCircle / ( 2 * sqrt(2) ))")
  dimension "d1318" diameter C1 = 8.0829 (= "2 * ( 7 mm ) / sqrt(3)")
extrude "Extrude19" new body sketch "Adapter Nut Hex 4" profile of L1 L2 L3 L4 L5 L6 along normal blind 3.2
sketch "Nut Thread Clearance 4" plane through (-3.182, -3.182, 0) normal (0.7071, 0.7071, 0) x axis (0, 0, 1)
  circle C1 centre (22.6274, -22.6274) radius 2.15
  point P1 (0, 0)
  point P2 (22.6274, -22.6274)
  dimension "d1321" distance P1 P2 = 22.6274 (= "abs(mountCircle / ( 2 * sqrt(2) ))")
  dimension "d1322" distance P1 P2 = 22.6274 (= "abs(-mountCircle / ( 2 * sqrt(2) ))")
  dimension "d1323" diameter C1 = 4.3
extrude "Extrude20" cut sketch "Nut Thread Clearance 4" along normal blind 3.2
work_plane "WorkPlane1" AlongDistance 0 ExtraOffset 0
sketch "M3 Pattern Axis" plane through (0, 0, 0) normal (0.7071, 0.7071, 0) x axis (0, 0, 1)
  circle C1 centre (0, 0) radius 0.5
  dimension "d1328" diameter C1 = 1
work_plane "WorkPlane2" AlongDistance -8.7 (= "qRearEnd + capThickness + 0.5 mm - 45 mm") ExtraOffset 0
sketch "M3 Shank Profile" plane through (-6.1518, -6.1518, 0) normal (0.7071, 0.7071, 0) x axis (0, 0, 1)
  line L1 (17, 0) -> (0, 0)
  circle C1 centre (17, 0) radius 1.5
  point P1 (0, 0)
  point P2 (17, 0)
  horizontal L1
  dimension "d1331" distance P1 P2 = 17 (= "supportCircle / 2")
  dimension "d1332" diameter C1 = 3
extrude "Extrude1" new body sketch "M3 Shank Profile" profile of C1 along normal blind 45
work_plane "WorkPlane3" AlongDistance 36.3 (= "qRearEnd + capThickness + 0.5 mm") ExtraOffset 0
sketch "M3 Head Profile" plane through (25.668, 25.668, 0) normal (0.7071, 0.7071, 0) x axis (0, 0, 1)
  line L1 (17, 0) -> (0, 0)
  circle C1 centre (17, 0) radius 2.75
  point P1 (0, 0)
  point P2 (17, 0)
  horizontal L1
  dimension "d1337" distance P1 P2 = 17 (= "supportCircle / 2")
  dimension "d1338" diameter C1 = 5.5
extrude "Extrude2" new body sketch "M3 Head Profile" profile of C1 along normal blind 3
work_plane "WorkPlane4" AlongDistance 35.8 (= "qRearEnd + capThickness") ExtraOffset 0
sketch "Rear M3 Washer Profile" plane through (25.3144, 25.3144, 0) normal (0.7071, 0.7071, 0) x axis (0, 0, 1)
  line L1 (17, 0) -> (0, 0)
  circle C1 centre (17, 0) radius 3.5
  circle C2 centre (17, 0) radius 1.65
  point P1 (0, 0)
  point P2 (17, 0)
  horizontal L1
  dimension "d1343" distance P1 P2 = 17 (= "supportCircle / 2")
  dimension "d1344" diameter C1 = 7
  dimension "d1345" diameter C2 = 3.3
extrude "Extrude3" new body sketch "Rear M3 Washer Profile" profile of C1 C2 along normal blind 0.5
work_plane "WorkPlane5" AlongDistance -3 (= "qFront - capThickness - 0.5 mm") ExtraOffset 0
sketch "Front M3 Washer Profile" plane through (-2.1213, -2.1213, 0) normal (0.7071, 0.7071, 0) x axis (0, 0, 1)
  line L1 (17, 0) -> (0, 0)
  circle C1 centre (17, 0) radius 3.5
  circle C2 centre (17, 0) radius 1.65
  point P1 (0, 0)
  point P2 (17, 0)
  horizontal L1
  dimension "d1350" distance P1 P2 = 17 (= "supportCircle / 2")
  dimension "d1351" diameter C1 = 7
  dimension "d1352" diameter C2 = 3.3
extrude "Extrude4" new body sketch "Front M3 Washer Profile" profile of C1 C2 along normal blind 0.5
work_plane "WorkPlane6" AlongDistance -7 (= "qFront - capThickness - 4.5 mm") ExtraOffset 0
sketch "Front M3 Nyloc Envelope Profile" plane through (-4.9497, -4.9497, 0) normal (0.7071, 0.7071, 0) x axis (0, 0, 1)
  line L1 (17, 0) -> (0, 0)
  circle C1 centre (17, 0) radius 3.18
  circle C2 centre (17, 0) radius 1.65
  point P1 (0, 0)
  point P2 (17, 0)
  horizontal L1
  dimension "d1357" distance P1 P2 = 17 (= "supportCircle / 2")
  dimension "d1358" diameter C1 = 6.36
  dimension "d1359" diameter C2 = 3.3
extrude "Extrude5" new body sketch "Front M3 Nyloc Envelope Profile" profile of C1 C2 along normal blind 4
circular_pattern "C-Pattern1" TotalAngle 360
work_plane "WorkPlane25" RotateAngle 90 ExtraOffset 0
work_plane "WorkPlane26" AlongDistance 75 (= "bodyWidth / 2") ExtraOffset 0
work_plane "WorkPlane27" AlongDistance -35 ExtraOffset 0
ground "Pin"
as_built_joint "As-built1" RotateMinimum 0 RotateMaximum 180
as_built_joint "As-built2"
as_built_joint "As-built3"
as_built_joint "As-built4"
as_built_joint "As-built5"
as_built_joint "As-built6"
as_built_joint "As-built7"
as_built_joint "As-built8"
as_built_joint "As-built9"
as_built_joint "As-built10"
as_built_joint "As-built11"
as_built_joint "As-built12"
as_built_joint "As-built13"
as_built_joint "As-built14"
as_built_joint "As-built15"
work_plane "WorkPlane33" AlongDistance -35 ExtraOffset 0
sketch "PRINT-FIRST-A0-rim Crop Footprint" plane through (0, 0, -35) normal (0, 0, 1) x axis (1, 0, 0)
  line L1 (130, 66.5) -> (55, 66.5)
  line L2 (130, 75) -> (130, 66.5)
  line L3 (55, 75) -> (130, 75)
  line L4 (55, 66.5) -> (55, 75)
  point P1 (0, 0)
  point P2 (55, 66.5)
  point P3 (130, 66.5)
  point P4 (130, 75)
  point P5 (55, 75)
  dimension "d1451" distance P1 P2 = 55 (= "abs(55 mm)")
  dimension "d1452" distance P1 P2 = 66.5 (= "abs(66.5 mm)")
  dimension "d1453" distance P1 P3 = 130 (= "abs(130 mm)")
  dimension "d1454" distance P1 P3 = 66.5 (= "abs(66.5 mm)")
  dimension "d1455" distance P1 P4 = 130 (= "abs(130 mm)")
  dimension "d1456" distance P1 P4 = 75 (= "abs(75 mm)")
  dimension "d1457" distance P1 P5 = 55 (= "abs(55 mm)")
  dimension "d1458" distance P1 P5 = 75 (= "abs(75 mm)")
extrude "Extrude46" sketch "PRINT-FIRST-A0-rim Crop Footprint" along normal blind 70
work_plane "WorkPlane34" AlongDistance 90.1 ExtraOffset 0
sketch "PRINT-FIRST-A0-rim Level Bed Boundary" plane through (63.7103, 63.7103, 0) normal (0.7071, 0.7071, 0) x axis (0, 0, 1)
  line L1 (200, -200) -> (-200, -200)
  line L2 (200, 200) -> (200, -200)
  line L3 (-200, 200) -> (200, 200)
  line L4 (-200, -200) -> (-200, 200)
  line L5 (200, 200) -> (-200, -200)
  point P1 (0, 0)
  point P2 (-200, -200)
  point P3 (200, -200)
  point P4 (200, 200)
  horizontal L1
  vertical L2
  horizontal L3
  vertical L4
  midpoint P1 L5
  dimension "d1463" distance P2 P3 = 400
  dimension "d1464" distance P3 P4 = 400
extrude "Extrude47" sketch "PRINT-FIRST-A0-rim Level Bed Boundary" profile of L1 L2 L3 L4 along normal blind 300
work_plane "WorkPlane35" AlongDistance 66.5 ExtraOffset 0
sketch "PRINT-FIRST-A90-brace Crop Footprint" plane through (0, 0, 66.5) normal (0, 0, 1) x axis (1, 0, 0)
  line L1 (130, -35) -> (48, -35)
  line L2 (130, 35) -> (130, -35)
  line L3 (48, 35) -> (130, 35)
  line L4 (48, -35) -> (48, 35)
  point P1 (0, 0)
  point P2 (48, -35)
  point P3 (130, -35)
  point P4 (130, 35)
  point P5 (48, 35)
  dimension "d1469" distance P1 P2 = 48 (= "abs(48 mm)")
  dimension "d1470" distance P1 P2 = 35 (= "abs(-35 mm)")
  dimension "d1471" distance P1 P3 = 130 (= "abs(130 mm)")
  dimension "d1472" distance P1 P3 = 35 (= "abs(-35 mm)")
  dimension "d1473" distance P1 P4 = 130 (= "abs(130 mm)")
  dimension "d1474" distance P1 P4 = 35 (= "abs(35 mm)")
  dimension "d1475" distance P1 P5 = 48 (= "abs(48 mm)")
  dimension "d1476" distance P1 P5 = 35 (= "abs(35 mm)")
extrude "Extrude48" sketch "PRINT-FIRST-A90-brace Crop Footprint" along normal blind 8.5 bodies "A Housing print (1)"
work_plane "WorkPlane36" AlongDistance 50.1 ExtraOffset 0
sketch "PRINT-FIRST-A90-brace Level Bed Boundary" plane through (35.426, 35.426, 0) normal (0.7071, 0.7071, 0) x axis (0, 0, 1)
  line L1 (200, -200) -> (-200, -200)
  line L2 (200, 200) -> (200, -200)
  line L3 (-200, 200) -> (200, 200)
  line L4 (-200, -200) -> (-200, 200)
  line L5 (200, 200) -> (-200, -200)
  point P1 (0, 0)
  point P2 (-200, -200)
  point P3 (200, -200)
  point P4 (200, 200)
  horizontal L1
  vertical L2
  horizontal L3
  vertical L4
  midpoint P1 L5
  dimension "d1481" distance P2 P3 = 400
  dimension "d1482" distance P3 P4 = 400
extrude "Extrude49" sketch "PRINT-FIRST-A90-brace Level Bed Boundary" profile of L1 L2 L3 L4 along normal blind 300
remove_body "RemoveBody1"
work_plane "WorkPlane28" RotateAngle 90 ExtraOffset 0
work_plane "WorkPlane29" AlongDistance 75 (= "bodyWidth / 2") ExtraOffset 0
sketch "B Driver Pad 1 Slot" plane through (0, -75, 0) normal (0, -1, 0) x axis (-1, 0, 0)
  line L1 (36.5, 28.6274) -> (43, 28.6274)
  line L2 (43, 16.6274) -> (36.5, 16.6274)
  line L3 (36.5, 22.6274) -> (43, 22.6274)
  arc A1 centre (36.5, 22.6274) radius 6 clockwise from (36.5, 16.6274) to (36.5, 28.6274)
  arc A2 centre (43, 22.6274) radius 6 clockwise from (43, 28.6274) to (43, 16.6274)
  point P2 (43, 22.6274)
  point P7 (43, 22.6274)
  point P1 (0, 0)
  point P8 (36.5, 22.6274)
  coincident P2 P7
  tangent L1 A1
  tangent A1 L2
  tangent L2 A2
  tangent L1 A2
  parallel L1 L2
  horizontal L3
  dimension "d1489" distance P1 P2 = 43 (= "Linear Dimension-2")
  dimension "d1490" distance P1 P2 = 22.6274 (= "Linear Dimension-3")
  dimension "d1491" diameter A1 = 12
  dimension "d1492" distance P7 P8 = 6.5
extrude "Extrude49" add sketch "B Driver Pad 1 Slot" profile of L1 A1 L2 A2 no distance stored
sketch "B Driver Pad 2 Slot" plane through (0, -75, 0) normal (0, -1, 0) x axis (-1, 0, 0)
  line L1 (36.5, -16.6274) -> (43, -16.6274)
  line L2 (43, -28.6274) -> (36.5, -28.6274)
  line L3 (36.5, -22.6274) -> (43, -22.6274)
  arc A1 centre (36.5, -22.6274) radius 6 clockwise from (36.5, -28.6274) to (36.5, -16.6274)
  arc A2 centre (43, -22.6274) radius 6 clockwise from (43, -16.6274) to (43, -28.6274)
  point P2 (43, -22.6274)
  point P7 (43, -22.6274)
  point P1 (0, 0)
  point P8 (36.5, -22.6274)
  coincident P2 P7
  tangent L1 A1
  tangent A1 L2
  tangent L2 A2
  tangent L1 A2
  parallel L1 L2
  horizontal L3
  dimension "d1495" distance P1 P2 = 43 (= "Linear Dimension-2")
  dimension "d1496" distance P1 P2 = 22.6274 (= "Linear Dimension-3")
  dimension "d1497" diameter A1 = 12
  dimension "d1498" distance P7 P8 = 6.5
extrude "Extrude50" add sketch "B Driver Pad 2 Slot" profile of L1 A1 L2 A2 no distance stored
sketch "B Driver Pad 3 Slot" plane through (0, -75, 0) normal (0, -1, 0) x axis (-1, 0, 0)
  line L1 (100.5, -16.6274) -> (107, -16.6274)
  line L2 (107, -28.6274) -> (100.5, -28.6274)
  line L3 (100.5, -22.6274) -> (107, -22.6274)
  arc A1 centre (100.5, -22.6274) radius 6 clockwise from (100.5, -28.6274) to (100.5, -16.6274)
  arc A2 centre (107, -22.6274) radius 6 clockwise from (107, -16.6274) to (107, -28.6274)
  point P2 (107, -22.6274)
  point P7 (107, -22.6274)
  point P1 (0, 0)
  point P8 (100.5, -22.6274)
  coincident P2 P7
  tangent L1 A1
  tangent A1 L2
  tangent L2 A2
  tangent L1 A2
  parallel L1 L2
  horizontal L3
  dimension "d1501" distance P1 P2 = 107 (= "Linear Dimension-2")
  dimension "d1502" distance P1 P2 = 22.6274 (= "Linear Dimension-3")
  dimension "d1503" diameter A1 = 12
  dimension "d1504" distance P7 P8 = 6.5
extrude "Extrude51" add sketch "B Driver Pad 3 Slot" profile of L1 A1 L2 A2 no distance stored
sketch "B Driver Pad 4 Slot" plane through (0, -75, 0) normal (0, -1, 0) x axis (-1, 0, 0)
  line L1 (100.5, 28.6274) -> (107, 28.6274)
  line L2 (107, 16.6274) -> (100.5, 16.6274)
  line L3 (100.5, 22.6274) -> (107, 22.6274)
  arc A1 centre (100.5, 22.6274) radius 6 clockwise from (100.5, 16.6274) to (100.5, 28.6274)
  arc A2 centre (107, 22.6274) radius 6 clockwise from (107, 28.6274) to (107, 16.6274)
  point P2 (107, 22.6274)
  point P7 (107, 22.6274)
  point P1 (0, 0)
  point P8 (100.5, 22.6274)
  coincident P2 P7
  tangent L1 A1
  tangent A1 L2
  tangent L2 A2
  tangent L1 A2
  parallel L1 L2
  horizontal L3
  dimension "d1507" distance P1 P2 = 107 (= "Linear Dimension-2")
  dimension "d1508" distance P1 P2 = 22.6274 (= "Linear Dimension-3")
  dimension "d1509" diameter A1 = 12
  dimension "d1510" distance P7 P8 = 6.5
extrude "Extrude52" add sketch "B Driver Pad 4 Slot" profile of L1 A1 L2 A2 no distance stored
work_plane "WorkPlane30" AlongDistance -35 ExtraOffset 0
sketch "B Mount Driver Axes" plane through (-24.7487, -24.7487, 0) normal (0.7071, 0.7071, 0) x axis (0, 0, 1)
  circle C1 centre (22.6274, 22.6274) radius 2.5
  circle C2 centre (-22.6274, 22.6274) radius 2.5
  circle C3 centre (-22.6274, -22.6274) radius 2.5
  circle C4 centre (22.6274, -22.6274) radius 2.5
  point P1 (0, 0)
  point P2 (22.6274, 22.6274)
  point P3 (-22.6274, 22.6274)
  point P4 (-22.6274, -22.6274)
  point P5 (22.6274, -22.6274)
  dimension "d1515" distance P1 P2 = 22.6274 (= "abs(mountCircle / ( 2 * sqrt(2) ))")
  dimension "d1516" distance P1 P2 = 22.6274 (= "abs(mountCircle / ( 2 * sqrt(2) ))")
  dimension "d1517" diameter C1 = 5 (= "driverPort")
  dimension "d1518" distance P1 P3 = 22.6274 (= "abs(-mountCircle / ( 2 * sqrt(2) ))")
  dimension "d1519" distance P1 P3 = 22.6274 (= "abs(mountCircle / ( 2 * sqrt(2) ))")
  dimension "d1520" diameter C2 = 5 (= "driverPort")
  dimension "d1521" distance P1 P4 = 22.6274 (= "abs(-mountCircle / ( 2 * sqrt(2) ))")
  dimension "d1522" distance P1 P4 = 22.6274 (= "abs(-mountCircle / ( 2 * sqrt(2) ))")
  dimension "d1523" diameter C3 = 5 (= "driverPort")
  dimension "d1524" distance P1 P5 = 22.6274 (= "abs(mountCircle / ( 2 * sqrt(2) ))")
  dimension "d1525" distance P1 P5 = 22.6274 (= "abs(-mountCircle / ( 2 * sqrt(2) ))")
  dimension "d1526" diameter C4 = 5 (= "driverPort")
extrude "Extrude53" cut sketch "B Mount Driver Axes" no distance stored
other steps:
base_feature "Base Feature1" bodies "B Moving Body print"
base_feature "Base Feature1" bodies "A Housing print"
create_component "CreateComponent1"
reparent_decal "ReparentDecal1"
remove_body "RemoveBody1"
create_component "CreateComponent2"
reparent_decal "ReparentDecal2"
remove_body "RemoveBody2"
create_component "CreateComponent3"
create_component "CreateComponent4"
create_component "CreateComponent5"
create_component "CreateComponent6"
create_component "CreateComponent7"
create_component "CreateComponent8"
create_component "CreateComponent9"
create_component "CreateComponent10"
create_component "CreateComponent11"
create_component "CreateComponent12"
create_component "CreateComponent13"
create_component "CreateComponent14"
create_component "CreateComponent15"
create_component "CreateComponent16"
named bodies: "A Housing print", "B Moving Body print", "A Housing print (1)"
